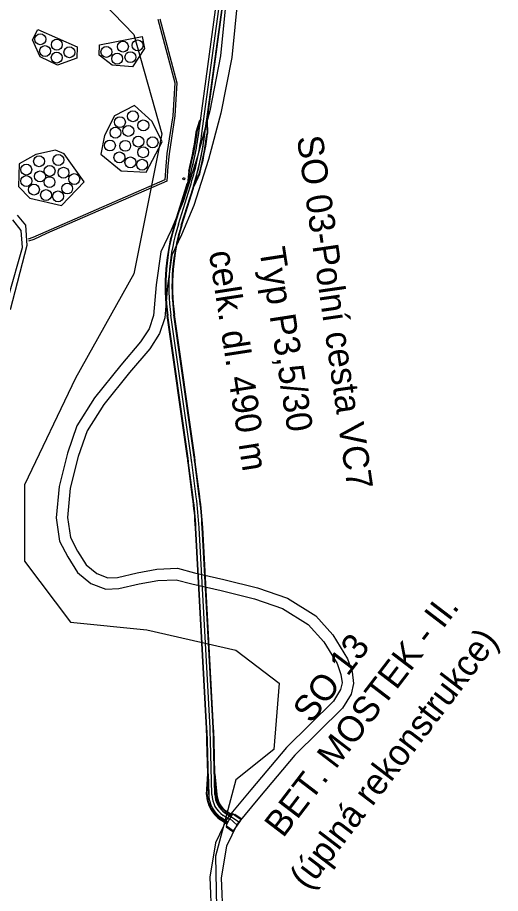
# Model space of a CAD drawing. Extents: x -551750 to -547457, y -1150683 to -1148508.
# Drawn here: x -550808.7 to -550575.1, y -1149495 to -1149071.2 of the extents above; entities that cross this region are included whole.
import ezdxf

# ---------------------------------------------------------------- set-up
doc = ezdxf.new("R2010")
doc.units = 0
for name, color, linetype in [('D02_ZaplUzemi20Vody', 7, 'Continuous'), ('D03_ZaplUzemi100Vody', 7, 'Continuous'), ('D05_AktivniZony100Vody', 7, 'Continuous'), ('u_ořez_na_hlavu', 7, 'Continuous'), ('u_popis_5000', 7, 'Continuous'), ('u_rekonstrukce mostu', 7, 'Continuous'), ('u_rekonstrukce_mostu_povrch', 7, 'Continuous'), ('u_VC15_srafa', 7, 'Continuous'), ('u_VC7_cesta', 7, 'Continuous'), ('u_VC7_osa', 7, 'Continuous'), ('u_VC7_srafa', 7, 'Continuous'), ('u_vypln_stromy', 7, 'Continuous'), ('u_vysadba', 7, 'Continuous'), ('u_vysadba kere', 7, 'Continuous')]:
    doc.layers.add(name, color=color, linetype=linetype)

msp = doc.modelspace()

# ---------------------------------------------------------------- linework, layer by layer
at = {"layer": 'D02_ZaplUzemi20Vody'}
msp.add_lwpolyline([(-550704.61, -1149029.83), (-550710.53, -1149089.8), (-550715.68, -1149116.29), (-550721.58, -1149138.42), (-550728.51, -1149160.28), (-550734.34, -1149174.03), (-550739.35, -1149184.51), (-550741.62, -1149200.46), (-550742.86, -1149215.35), (-550745, -1149221.76), (-550749.13, -1149228.14), (-550758.76, -1149239.47), (-550771.39, -1149255.15), (-550780.02, -1149268.78), (-550784.58, -1149282), (-550788.58, -1149298.03), (-550789.96, -1149313.2), (-550788.33, -1149324.52), (-550784.38, -1149332.14), (-550779.63, -1149339.7), (-550773.16, -1149344.94), (-550765.96, -1149347.83), (-550759.64, -1149347.5), (-550749.78, -1149345.22), (-550740.75, -1149343.6), (-550731.94, -1149343.17), (-550724.36, -1149345.18), (-550710.18, -1149348.36), (-550694.1, -1149352.44), (-550680.51, -1149357.05), (-550668.04, -1149364.85), (-550660.59, -1149373.19), (-550654.08, -1149383.74), (-550652.26, -1149388.99), (-550651.73, -1149393.05), (-550652.52, -1149396.37), (-550655.88, -1149401.89), (-550678.52, -1149424.31), (-550695.77, -1149444.77), (-550707.17, -1149458.39), (-550712.93, -1149470.4), (-550715.71, -1149487.12), (-550714.83, -1149507.47)], dxfattribs=at)
at = {"layer": 'D03_ZaplUzemi100Vody'}
msp.add_lwpolyline([(-550699.12, -1149030.01), (-550705.1, -1149090.59), (-550710.34, -1149117.52), (-550716.32, -1149139.96), (-550723.36, -1149162.18), (-550729.34, -1149176.29), (-550734.04, -1149186.12), (-550736.18, -1149201.07), (-550737.46, -1149216.46), (-550740.02, -1149224.15), (-550744.72, -1149231.42), (-550754.55, -1149242.96), (-550766.93, -1149258.35), (-550775.05, -1149271.17), (-550779.32, -1149283.56), (-550783.17, -1149298.95), (-550784.45, -1149313.05), (-550783.04, -1149322.82), (-550779.63, -1149329.42), (-550775.48, -1149336.01), (-550770.35, -1149340.16), (-550765.04, -1149342.3), (-550760.4, -1149342.06), (-550750.88, -1149339.86), (-550741.37, -1149338.15), (-550731.36, -1149337.66), (-550723.06, -1149339.86), (-550708.9, -1149343.03), (-550692.55, -1149347.19), (-550678.15, -1149352.07), (-550664.48, -1149360.62), (-550656.18, -1149369.9), (-550649.1, -1149381.38), (-550646.91, -1149387.73), (-550646.17, -1149393.34), (-550647.39, -1149398.47), (-550651.54, -1149405.31), (-550674.49, -1149428.03), (-550691.57, -1149448.3), (-550702.53, -1149461.38), (-550707.65, -1149472.06), (-550710.21, -1149487.45), (-550709.36, -1149507.11)], dxfattribs=at)
at = {"layer": 'D05_AktivniZony100Vody'}
msp.add_lwpolyline([(-550786.8, -1149043.8), (-550752.35, -1149079.49), (-550738.81, -1149127.48), (-550752.35, -1149195.16), (-550780.65, -1149245.61), (-550805.26, -1149297.3), (-550805.26, -1149334.21), (-550783.11, -1149363.74), (-550746.2, -1149367.44), (-550703.13, -1149377.28), (-550682.21, -1149393.28), (-550684.67, -1149425.27), (-550703.13, -1149440.04), (-550712.97, -1149476.95), (-550711.74, -1149534.79)], dxfattribs=at)
at = {"layer": 'u_ořez_na_hlavu'}
for points in [[(-550812.8, -1149205.69), (-550806.26, -1149182.4), (-550806.9, -1149174.3), (-550810.89, -1149169.06)], [(-550808.83, -1149166.78), (-550804.77, -1149171.73), (-550804.1, -1149181.57), (-550812.2, -1149212.56)]]:
    msp.add_lwpolyline(points, dxfattribs=at)
at = {"layer": 'u_rekonstrukce mostu'}
for p, q in [((-550703.56, -1149456.58), (-550703.84, -1149456.99)), ((-550703.84, -1149456.99), (-550700.54, -1149459.26)), ((-550703.56, -1149456.58), (-550700.26, -1149458.85)), ((-550700.26, -1149458.85), (-550700.54, -1149459.26)), ((-550707.56, -1149462.32), (-550707.85, -1149462.73)), ((-550707.85, -1149462.73), (-550704.54, -1149465.01)), ((-550707.56, -1149462.32), (-550704.26, -1149464.59)), ((-550704.26, -1149464.59), (-550704.54, -1149465.01))]:
    msp.add_line(p, q, dxfattribs=at)
at = {"layer": 'u_rekonstrukce_mostu_povrch'}
msp.add_lwpolyline([(-550704.72, -1149456.41), (-550706.24, -1149459.17), (-550707.84, -1149462.13), (-550704.26, -1149464.59), (-550701.24, -1149460.27), (-550700.54, -1149459.26)], close=True, dxfattribs=at)
at = {"layer": 'u_VC15_srafa'}
msp.add_line((-550702.39, -1149461.86), (-550706, -1149458.74), dxfattribs=at)
at = {"layer": 'u_VC7_cesta'}
for p, q in [((-550721.2, -1149128.27), (-550704.65, -1149006.61)), ((-550718.23, -1149128.68), (-550701.67, -1149007.01)), ((-550716.96, -1149121.19), (-550701.43, -1149007.05)), ((-550722.23, -1149126.52), (-550720.44, -1149120.8)), ((-550721.98, -1149126.58), (-550720.19, -1149120.85)), ((-550717.21, -1149121.17), (-550717.03, -1149127.25)), ((-550716.96, -1149121.19), (-550716.78, -1149127.27)), ((-550722.44, -1149128.1), (-550722.23, -1149126.52)), ((-550722.19, -1149128.14), (-550721.98, -1149126.58)), ((-550717.24, -1149128.81), (-550717.03, -1149127.25)), ((-550716.99, -1149128.85), (-550716.78, -1149127.27)), ((-550725.88, -1149145.48), (-550726.53, -1149151.44)), ((-550725.64, -1149145.53), (-550726.28, -1149151.49)), ((-550723.4, -1149152.31), (-550720.8, -1149146.79)), ((-550723.16, -1149152.4), (-550720.56, -1149146.88)), ((-550732.57, -1149170.7), (-550726.9, -1149152.64)), ((-550732.33, -1149170.77), (-550726.66, -1149152.72)), ((-550729.47, -1149171.67), (-550723.8, -1149153.61)), ((-550729.47, -1149171.67), (-550723.8, -1149153.61)), ((-550729.23, -1149171.74), (-550723.56, -1149153.69)), ((-550726.46, -1149284.38), (-550736.23, -1149215.44)), ((-550726.22, -1149284.35), (-550735.98, -1149215.4)), ((-550723.25, -1149283.93), (-550733.01, -1149214.98)), ((-550723.25, -1149283.93), (-550733.01, -1149214.98)), ((-550723, -1149283.89), (-550732.76, -1149214.94)), ((-550723.98, -1149303.37), (-550726.16, -1149286.61)), ((-550723.73, -1149303.34), (-550725.91, -1149286.58)), ((-550720.76, -1149302.95), (-550722.94, -1149286.19)), ((-550720.76, -1149302.95), (-550722.94, -1149286.19)), ((-550720.51, -1149302.92), (-550722.69, -1149286.16)), ((-550717.32, -1149415.12), (-550722.62, -1149318.14)), ((-550717.07, -1149415.1), (-550722.37, -1149318.13)), ((-550714.08, -1149414.94), (-550719.37, -1149317.96)), ((-550714.08, -1149414.94), (-550719.37, -1149317.96)), ((-550713.83, -1149414.93), (-550719.12, -1149317.95)), ((-550716.71, -1149437.15), (-550717.09, -1149421.2)), ((-550716.22, -1149447.13), (-550716.84, -1149421.2)), ((-550713.22, -1149447.06), (-550713.84, -1149421.13)), ((-550713.22, -1149447.06), (-550713.84, -1149421.13)), ((-550713.21, -1149437.09), (-550713.59, -1149421.12)), ((-550717.22, -1149447.15), (-550716.71, -1149437.15)), ((-550716.97, -1149447.16), (-550716.46, -1149437.15)), ((-550713.46, -1149437.11), (-550712.47, -1149447.06)), ((-550713.21, -1149437.09), (-550712.22, -1149447.03)), ((-550701.33, -1149460.66), (-550708.35, -1149455.94)), ((-550705.16, -1149457.19), (-550707.94, -1149455.32)), ((-550705.04, -1149456.97), (-550707.8, -1149455.11)), ((-550707.44, -1149461.38), (-550710.58, -1149459.27)), ((-550707.32, -1149461.16), (-550710.44, -1149459.06)), ((-550706.96, -1149460.5), (-550710.03, -1149458.44)), ((-550703.56, -1149463.98), (-550703.74, -1149463.86)), ((-550703.42, -1149463.78), (-550703.6, -1149463.65)), ((-550703, -1149463.15), (-550703.17, -1149463.04))]:
    msp.add_line(p, q, dxfattribs=at)
msp.add_circle((-550728.21, -1149149.2), 0.5, dxfattribs=at)
for centre, radius, start, end in [((-550868.35, -1149108.25), 148.5, 342.5757, 352.2503), ((-550868.35, -1149108.25), 147.25, 345.3528, 352.2503), ((-550868.35, -1149108.25), 147.5, 345.36, 352.2503), ((-550868.35, -1149108.25), 151.5, 342.5757, 352.2503), ((-550868.35, -1149108.25), 152.5, 345.36, 352.2503), ((-550868.35, -1149108.25), 152.75, 345.3513, 352.2503), ((-550868.35, -1149108.25), 148.25, 342.5757, 343.0604), ((-550868.35, -1149108.25), 151.75, 342.5757, 343.0838), ((-550635.49, -1149201.17), 101.75, 162.5757, 188.062), ((-550635.49, -1149201.17), 101.5, 162.5757, 188.062), ((-550635.49, -1149201.17), 98.5, 162.5757, 188.062), ((-550635.49, -1149201.17), 98.5, 162.5757, 188.062), ((-550635.49, -1149201.17), 98.25, 162.5757, 188.062), ((-550922.75, -1149312.19), 198.25, 7.4126, 8.062), ((-550922.75, -1149312.19), 198.5, 7.4126, 8.062), ((-550922.75, -1149312.19), 201.5, 7.4126, 8.062), ((-550922.75, -1149312.19), 201.5, 7.4126, 8.062), ((-550922.75, -1149312.19), 201.75, 7.4126, 8.062), ((-550920.57, -1149328.95), 198.25, 3.1249, 7.4126), ((-550920.57, -1149328.95), 198.5, 3.1249, 7.4126), ((-550920.57, -1149328.95), 201.5, 3.1249, 7.4126), ((-550920.57, -1149328.95), 201.5, 3.1249, 7.4126), ((-550920.57, -1149328.95), 201.75, 3.1249, 7.4126), ((-550915.28, -1149425.92), 198.25, 1.3645, 3.1249), ((-550915.28, -1149425.92), 198.5, 1.3645, 3.1249), ((-550915.28, -1149425.92), 201.5, 1.3645, 3.1249), ((-550915.28, -1149425.92), 201.5, 1.3645, 3.1249), ((-550915.28, -1149425.92), 201.75, 1.3645, 3.1249), ((-550702.22, -1149446.81), 15, 181.3645, 236.1175), ((-550702.22, -1149446.81), 14.75, 181.3645, 236.1175), ((-550702.22, -1149446.81), 14, 181.3645, 236.1175), ((-550702.22, -1149446.81), 11, 181.3645, 236.1175), ((-550702.22, -1149446.81), 10.25, 181.3645, 236.1175), ((-550702.22, -1149446.81), 10, 181.3645, 236.1175)]:
    msp.add_arc(centre, radius, start, end, dxfattribs=at)
at = {"layer": 'u_VC7_osa'}
for points in [[(-550719.72, -1149128.48), (-550703.16, -1149006.81)], [(-550730.9, -1149171.22), (-550725.23, -1149153.17)], [(-550724.73, -1149284.14), (-550734.5, -1149215.19)], [(-550722.25, -1149303.14), (-550724.43, -1149286.38)], [(-550715.58, -1149415.02), (-550720.87, -1149318.04)], [(-550714.72, -1149447.11), (-550715.34, -1149421.16)], [(-550706.24, -1149459.17), (-550709.19, -1149457.19)]]:
    msp.add_lwpolyline(points, dxfattribs=at)
for centre, radius, start, end in [((-550868.35, -1149108.25), 150, 342.5757, 352.2503), ((-550635.49, -1149201.17), 100, 162.5757, 188.062), ((-550922.75, -1149312.19), 200, 7.4126, 8.062), ((-550920.57, -1149328.95), 200, 3.1249, 7.4126), ((-550915.28, -1149425.92), 200, 1.3645, 3.1249), ((-550702.22, -1149446.81), 12.5, 181.3645, 236.1175)]:
    msp.add_arc(centre, radius, start, end, dxfattribs=at)
at = {"layer": 'u_VC7_srafa'}
for points in [[(-550720.1, -1149120.35), (-550721.98, -1149126.58), (-550722.36, -1149129.32), (-550723.11, -1149134), (-550723.64, -1149136.81), (-550724.14, -1149139.24), (-550724.95, -1149142.78), (-550725.64, -1149145.53), (-550726.28, -1149151.49), (-550725.58, -1149149.1), (-550724.65, -1149145.72), (-550723.37, -1149140.44), (-550722.78, -1149137.64), (-550722.09, -1149134.06), (-550721.4, -1149129.86), (-550721.12, -1149127.86), (-550720.1, -1149120.35)], [(-550717.21, -1149121.17), (-550717.03, -1149127.25), (-550717.24, -1149128.81), (-550717.63, -1149131.49), (-550718.39, -1149136.01), (-550718.78, -1149138.01), (-550719.51, -1149141.48), (-550720.8, -1149146.79), (-550723.4, -1149152.31), (-550722.69, -1149149.92), (-550721.77, -1149146.54), (-550720.49, -1149141.26), (-550719.89, -1149138.46), (-550719.21, -1149134.88), (-550718.52, -1149130.68), (-550718.23, -1149128.68), (-550717.21, -1149121.17)], [(-550707.32, -1149461.16), (-550710.44, -1149459.06), (-550712.28, -1149457.6), (-550713.37, -1149456.47), (-550714.27, -1149455.32), (-550715.72, -1149452.75), (-550716.31, -1149451.17), (-550716.79, -1149449.11), (-550716.97, -1149447.16), (-550716.46, -1149437.15), (-550716.22, -1149447.13), (-550716.14, -1149448.34), (-550715.96, -1149449.49), (-550715.85, -1149450.01), (-550715.31, -1149451.77), (-550714.76, -1149453.03), (-550714.17, -1149454.1), (-550713.5, -1149455.1), (-550712.48, -1149456.34), (-550711.05, -1149457.68), (-550710.03, -1149458.44), (-550706.96, -1149460.5)], [(-550713.46, -1149437.11), (-550713.22, -1149447.07), (-550713.12, -1149448.32), (-550712.85, -1149449.65), (-550712.42, -1149450.94), (-550711.96, -1149451.93), (-550711.15, -1149453.24), (-550710.21, -1149454.38), (-550709.61, -1149454.96), (-550708.63, -1149455.75), (-550708.35, -1149455.94), (-550705.52, -1149457.85), (-550705.16, -1149457.19), (-550707.94, -1149455.32), (-550709.34, -1149454.18), (-550710.33, -1149453.08), (-550710.88, -1149452.3), (-550711.58, -1149451), (-550712.1, -1149449.55), (-550712.37, -1149448.26), (-550712.44, -1149447.61), (-550712.47, -1149447.06)]]:
    msp.add_lwpolyline(points, close=True, dxfattribs=at)
at = {"layer": 'u_vypln_stromy'}
for points in [[(-550798.91, -1149076.97), (-550779.88, -1149085.32), (-550779.93, -1149090.95), (-550789.37, -1149094.31), (-550797.69, -1149090.3), (-550801.41, -1149082.06)], [(-550768.98, -1149084.36), (-550748.34, -1149080.44), (-550747.27, -1149086.14), (-550753.13, -1149095.02), (-550762.95, -1149094.24), (-550769.13, -1149089.51)], [(-550768.44, -1149137.34), (-550758.55, -1149145.45), (-550746.48, -1149146.09), (-550738.75, -1149131.42), (-550743.59, -1149121.55), (-550752.06, -1149113.75), (-550761.79, -1149118.83), (-550766.58, -1149128.25)], [(-550787.4, -1149162.15), (-550776.47, -1149150.7), (-550786.06, -1149137.22), (-550790.31, -1149135.39), (-550799.9, -1149137.41), (-550807.92, -1149142.05), (-550808.15, -1149152.98), (-550802.67, -1149158.63)]]:
    msp.add_lwpolyline(points, close=True, dxfattribs=at)
at = {"layer": 'u_vysadba'}
for centre in [(-550797.66, -1149081.75), (-550789.66, -1149084.35), (-550757.69, -1149085.29), (-550750.61, -1149084.71), (-550795.34, -1149087.46), (-550789.69, -1149090.62), (-550783.57, -1149088.01), (-550765.7, -1149087.84), (-550760.49, -1149091.13), (-550754.06, -1149090.4), (-550752.85, -1149118.96), (-550759.17, -1149121.85), (-550747.84, -1149123.39), (-550761.31, -1149126.91), (-550755.1, -1149126.09), (-550764, -1149133.12), (-550756.6, -1149133.28), (-550750.23, -1149131.26), (-550743.37, -1149131.6), (-550747.9, -1149136.42), (-550798.24, -1149140.74), (-550788.91, -1149140.15), (-550759.38, -1149138.88), (-550754.08, -1149141.29), (-550804.47, -1149144.77), (-550793.16, -1149145.43), (-550786.45, -1149146.3), (-550748.45, -1149142.45), (-550804.42, -1149150.36), (-550797.8, -1149148.08), (-550793.22, -1149150.85), (-550781.22, -1149149.35), (-550800.73, -1149154.44), (-550784.65, -1149153.95), (-550794.87, -1149157.11), (-550789.08, -1149157.74)]:
    msp.add_circle(centre, 2.64, dxfattribs=at)
at = {"layer": 'u_vysadba kere'}
for points in [[(-550739.8, -1149071.82), (-550731.62, -1149102.76), (-550732.61, -1149118.81), (-550735.4, -1149137.14), (-550735.91, -1149143.14), (-550736.49, -1149150.37), (-550794.61, -1149175.76), (-550800.83, -1149178.54), (-550803.42, -1149179.45)], [(-550740.77, -1149072.07), (-550732.62, -1149102.86), (-550733.61, -1149118.7), (-550736.4, -1149137.02), (-550736.91, -1149143.06), (-550737.44, -1149149.69), (-550795.02, -1149174.85), (-550801.2, -1149177.61), (-550803.58, -1149178.45)]]:
    msp.add_lwpolyline(points, dxfattribs=at)

# ---------------------------------------------------------------- texts
at = {"layer": 'u_popis_5000'}
for s, rotation, p in [('SO 03-Polní cesta VC7', 278.1872, (-550673.63, -1149129.15)), ('Typ P3,5/30', 278.8161, (-550691.78, -1149183.29)), ('celk. dl. 490 m', 278.8161, (-550716.18, -1149184.79)), ('BET. MOSTEK - II.', 52.5975, (-550680.25, -1149468.47)), ('(úplná rekonstrukce)', 52.5975, (-550668.18, -1149493.85)), ('SO 13', 52.5975, (-550666.54, -1149413.2))]:
    msp.add_text(s, height=12.5, rotation=rotation, dxfattribs=at).set_placement(p)

doc.saveas('drawing.dxf')
